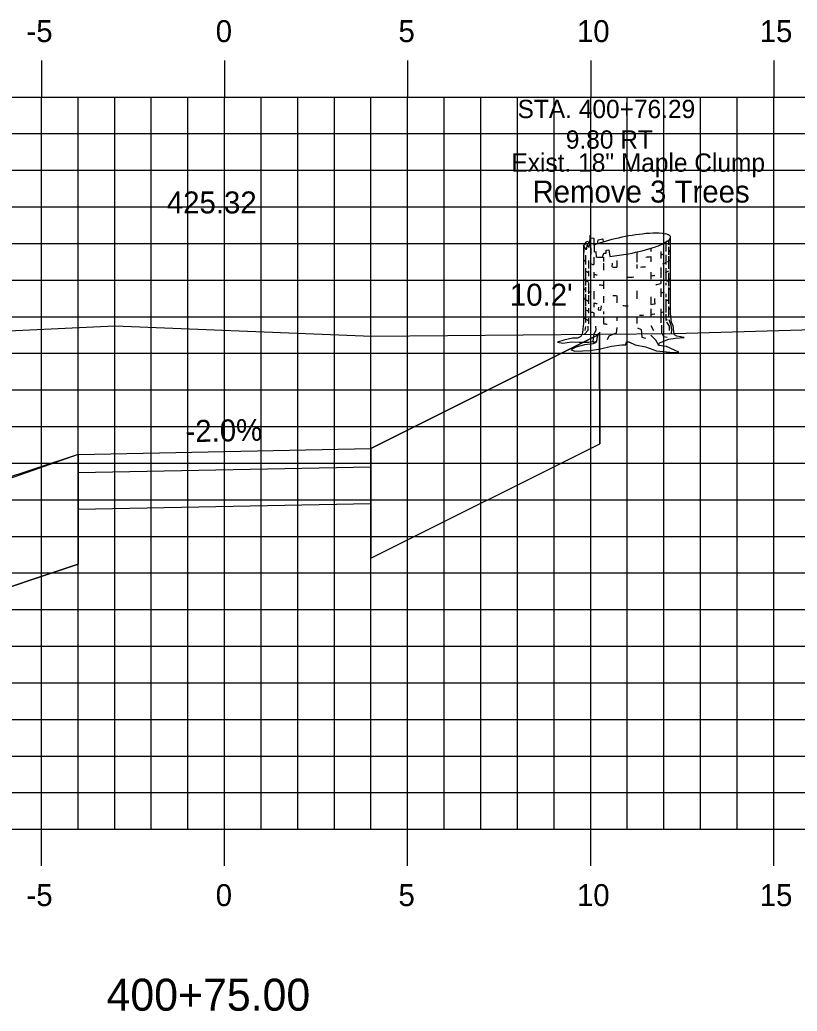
# Model space of a CAD drawing. Extents: x -161 to 764, y 111 to 210.
# Drawn here: x 405 to 426.23, y 171.28 to 198.36 of the extents above; entities that cross this region are included whole.
import ezdxf

# ---------------------------------------------------------------- set-up
doc = ezdxf.new("R2010")
doc.units = 0
for name, color, linetype in [('D_Property_Walkway_Paved', 7, 'Continuous'), ('D_Roadway_Centerline_Text', 7, 'Continuous'), ('D_Roadway_SubGrade', 7, 'Continuous'), ('D_Slope_Cut', 7, 'Continuous'), ('D_Text_Monospaced', 7, 'Continuous'), ('D_Text_Standard', 7, 'Continuous'), ('H_V ANNOTATION', 7, 'Continuous'), ('MAJOR', 7, 'Continuous'), ('MINOR', 7, 'Continuous'), ('PATTERNING', 7, 'Continuous'), ('S_Roadway_Centerline', 7, 'Continuous'), ('S_Trees_Decid_Pay', 7, 'Continuous')]:
    doc.layers.add(name, color=color, linetype=linetype)

msp = doc.modelspace()

# ---------------------------------------------------------------- linework, layer by layer
at = {"layer": 'D_Property_Walkway_Paved'}
for p, q in [((414.591, 186.147), (414.591, 186.647)), ((406.591, 186.487), (406.591, 185.987))]:
    msp.add_line(p, q, dxfattribs=at)
for points in [[(406.591, 186.487), (414.591, 186.647)], [(406.591, 185.987), (414.591, 186.147)]]:
    msp.add_lwpolyline(points, dxfattribs=at)
at = {"layer": 'D_Roadway_SubGrade'}
msp.add_line((414.591, 185.147), (414.591, 186.147), dxfattribs=at)
msp.add_lwpolyline([(406.591, 185.987), (406.591, 184.987), (414.591, 185.147)], dxfattribs=at)
at = {"layer": 'D_Slope_Cut'}
for p, q in [((414.591, 186.647), (420.832, 189.768)), ((420.832, 189.768), (420.845, 186.774)), ((406.591, 186.487), (403.591, 185.487)), ((406.591, 186.487), (406.591, 183.487))]:
    msp.add_line(p, q, dxfattribs=at)
for points in [[(414.591, 186.647), (414.591, 183.647), (420.845, 186.774)], [(406.591, 183.487), (403.591, 182.487), (395.592, 186.488)]]:
    msp.add_lwpolyline(points, dxfattribs=at)
at = {"layer": 'MAJOR'}
for p, q in [((405.591, 197.249), (405.591, 196.247)), ((410.591, 197.249), (410.591, 196.247)), ((415.591, 197.249), (415.591, 196.247)), ((420.591, 197.249), (420.591, 196.247)), ((425.591, 197.249), (425.591, 196.247)), ((340.591, 196.247), (480.591, 196.247)), ((340.591, 196.247), (480.591, 196.247)), ((405.591, 176.247), (405.591, 196.247)), ((410.591, 176.247), (410.591, 196.247)), ((415.591, 176.247), (415.591, 196.247)), ((420.591, 176.247), (420.591, 196.247)), ((425.591, 176.247), (425.591, 196.247)), ((340.591, 191.247), (480.591, 191.247)), ((340.591, 186.247), (480.591, 186.247)), ((340.591, 181.247), (480.591, 181.247)), ((340.591, 176.247), (480.591, 176.247)), ((340.591, 176.247), (480.591, 176.247)), ((405.591, 175.245), (405.591, 176.247)), ((410.591, 175.245), (410.591, 176.247)), ((415.591, 175.245), (415.591, 176.247)), ((420.591, 175.245), (420.591, 176.247)), ((425.591, 175.245), (425.591, 176.247))]:
    msp.add_line(p, q, dxfattribs=at)
at = {"layer": 'MINOR'}
for p, q in [((406.591, 176.247), (406.591, 196.247)), ((407.591, 176.247), (407.591, 196.247)), ((408.591, 176.247), (408.591, 196.247)), ((409.591, 176.247), (409.591, 196.247)), ((411.591, 176.247), (411.591, 196.247)), ((412.591, 176.247), (412.591, 196.247)), ((413.591, 176.247), (413.591, 196.247)), ((414.591, 176.247), (414.591, 196.247)), ((416.591, 176.247), (416.591, 196.247)), ((417.591, 176.247), (417.591, 196.247)), ((418.591, 176.247), (418.591, 196.247)), ((419.591, 176.247), (419.591, 196.247)), ((421.591, 176.247), (421.591, 196.247)), ((422.591, 176.247), (422.591, 196.247)), ((423.591, 176.247), (423.591, 196.247)), ((424.591, 176.247), (424.591, 196.247)), ((340.591, 195.247), (480.591, 195.247)), ((340.591, 194.247), (480.591, 194.247)), ((340.591, 193.247), (480.591, 193.247)), ((340.591, 192.247), (480.591, 192.247)), ((340.591, 190.247), (480.591, 190.247)), ((340.591, 189.247), (480.591, 189.247)), ((340.591, 188.247), (480.591, 188.247)), ((340.591, 187.247), (480.591, 187.247)), ((340.591, 185.247), (480.591, 185.247)), ((340.591, 184.247), (480.591, 184.247)), ((340.591, 183.247), (480.591, 183.247)), ((340.591, 182.247), (480.591, 182.247)), ((340.591, 180.247), (480.591, 180.247)), ((340.591, 179.247), (480.591, 179.247)), ((340.591, 178.247), (480.591, 178.247)), ((340.591, 177.247), (480.591, 177.247))]:
    msp.add_line(p, q, dxfattribs=at)
at = {"layer": 'PATTERNING'}
for points in [[(414.591, 186.647), (414.591, 183.647), (420.845, 186.774), (420.832, 189.768)], [(395.597, 189.484), (395.592, 186.488), (403.591, 182.487), (406.591, 183.487), (406.591, 186.487), (403.592, 185.431)]]:
    msp.add_lwpolyline(points, close=True, dxfattribs=at)
at = {"layer": 'S_Roadway_Centerline'}
msp.add_lwpolyline([(340.591, 183.558), (346.27, 184.146), (348.315, 184.806), (354.074, 186.337), (357.168, 187.075), (364.507, 188.564), (366.124, 189.037), (373.039, 189.084), (380.424, 189.717), (384.106, 189.757), (390.092, 189.37), (397.718, 189.529), (407.599, 189.997), (414.618, 189.716), (422.879, 189.785), (430.793, 190.018)], dxfattribs=at)
at = {"layer": 'S_Trees_Decid_Pay'}
for p, q in [((422.64, 192.283), (422.64, 192.03)), ((422.72, 192.327), (422.72, 192.207)), ((420.595, 192.124), (420.595, 191.95)), ((421.852, 192.015), (421.852, 191.735)), ((422.235, 192.116), (422.235, 192.03)), ((422.507, 192.03), (422.507, 191.838)), ((422.72, 192.155), (422.72, 191.941)), ((420.446, 191.924), (420.446, 191.669)), ((420.532, 191.778), (420.532, 191.566)), ((420.68, 191.875), (420.68, 191.671)), ((420.941, 191.877), (420.941, 191.758)), ((421.306, 191.778), (421.306, 191.598)), ((422.235, 191.888), (422.235, 191.749)), ((422.64, 191.933), (422.64, 191.669)), ((422.72, 191.896), (422.72, 191.558)), ((420.446, 191.572), (420.446, 191.103)), ((420.532, 191.501), (420.532, 191.352)), ((420.68, 191.463), (420.68, 191.309)), ((420.941, 191.706), (420.941, 191.521)), ((421.179, 191.606), (421.185, 191.713)), ((421.852, 191.669), (421.852, 191.566)), ((422.235, 191.463), (422.235, 191.272)), ((422.507, 191.587), (422.507, 191.309)), ((422.64, 191.572), (422.64, 191.264)), ((420.532, 191.175), (420.532, 190.875)), ((420.941, 191.235), (420.941, 191.007)), ((422.507, 191.264), (422.507, 191.155)), ((422.64, 191.175), (422.64, 191.109)), ((422.72, 191.441), (422.72, 191.08)), ((420.446, 191.052), (420.446, 190.918)), ((420.68, 190.946), (420.68, 190.726)), ((421.852, 190.955), (421.852, 190.734)), ((422.507, 191.02), (422.507, 190.792)), ((422.72, 191.043), (422.72, 190.595)), ((420.446, 190.86), (420.446, 190.535)), ((420.532, 190.837), (420.532, 190.595)), ((420.941, 190.808), (420.941, 190.623)), ((421.306, 190.82), (421.306, 190.623)), ((422.235, 190.792), (422.235, 190.584)), ((422.64, 190.875), (422.64, 190.778)), ((422.64, 190.726), (422.64, 190.366)), ((420.446, 190.506), (420.446, 190.086)), ((420.532, 190.484), (420.532, 190.343)), ((420.68, 190.627), (420.68, 190.506)), ((420.941, 190.388), (420.941, 190.312)), ((422.235, 190.463), (422.235, 190.263)), ((422.507, 190.463), (422.507, 190.079)), ((422.72, 190.529), (422.72, 190.247)), ((420.532, 190.211), (420.532, 190.055)), ((420.68, 190.355), (420.68, 190.257)), ((420.941, 190.234), (420.941, 190.061)), ((421.306, 190.24), (421.306, 190.137)), ((421.852, 190.234), (421.852, 190.061)), ((422.64, 190.314), (422.64, 190.148)), ((420.449, 189.983), (420.435, 189.866)), ((422.23, 190.006), (422.311, 189.874))]:
    msp.add_line(p, q, dxfattribs=at)
for points in [[(420.395, 192.198), (420.395, 190.061), (420.375, 189.919), (420.369, 189.793), (420.326, 189.707), (420.233, 189.658), (420.097, 189.658), (419.854, 189.602), (419.687, 189.553), (419.83, 189.522), (420.066, 189.559), (420.276, 189.547), (420.538, 189.553), (420.662, 189.571), (420.692, 189.528), (420.754, 189.571), (420.655, 189.503), (420.42, 189.478), (420.19, 189.417), (420.06, 189.346), (420.159, 189.303), (420.581, 189.322), (420.859, 189.366), (421.158, 189.442), (421.444, 189.478), (421.549, 189.478), (421.567, 189.559), (421.635, 189.565), (421.802, 189.478), (422.088, 189.423), (422.387, 189.316), (422.846, 189.266), (423, 189.279), (422.658, 189.429), (422.455, 189.46), (422.467, 189.534), (422.727, 189.633), (422.902, 189.664), (423.143, 189.676), (422.944, 189.713), (422.883, 189.75), (422.858, 189.837), (422.846, 190.006), (422.801, 190.092), (422.772, 190.333), (422.772, 192.419)], [(420.751, 191.871), (420.744, 192.015), (420.698, 192.007), (420.684, 192.382), (420.589, 192.39), (420.575, 192.47), (420.538, 192.133), (420.492, 192.227), (420.472, 192.073), (420.395, 192.198), (420.401, 192.009)], [(420.395, 192.198), (420.441, 192.221), (420.463, 192.287), (420.515, 192.31), (420.549, 192.235)], [(420.774, 192.237), (420.795, 192.345), (420.927, 192.375), (420.934, 192.287)], [(420.913, 191.875), (420.95, 191.978), (421.015, 191.984), (421.015, 192.066), (421.089, 192.073), (421.114, 191.892)], [(422.349, 190.598), (422.347, 190.675), (422.339, 190.741)], [(420.803, 190.506), (420.795, 190.432), (420.869, 190.426), (420.883, 190.543)], [(422.665, 190.094), (422.736, 189.991), (422.736, 189.866)], [(422.722, 190.175), (422.782, 190.014), (422.796, 189.888), (422.788, 189.791)], [(420.515, 189.991), (420.509, 189.866), (420.427, 189.771)], [(420.662, 189.571), (420.68, 189.75), (420.742, 189.887), (420.735, 189.987)], [(421.304, 189.954), (421.287, 189.8), (421.089, 189.719), (421.044, 189.616)], [(421.87, 189.946), (421.973, 189.894), (421.987, 189.688), (422.09, 189.659)], [(422.524, 190.02), (422.524, 189.814), (422.582, 189.705), (422.679, 189.688)], [(420.853, 189.818), (420.778, 189.75), (420.76, 189.652), (420.754, 189.571)], [(422.455, 189.46), (422.368, 189.602), (422.236, 189.744)]]:
    msp.add_lwpolyline(points, dxfattribs=at)
for centre, radius, start, end in [((422.685, 186.417), 6.126, 93.6944, 100.7779), ((422.374, 191.233), 1.299, 78.2779, 93.6944), ((422.685, 186.417), 6.126, 100.7779, 107.8613), ((421.963, 193.392), 1.299, 287.8613, 303.2779), ((422.541, 192.036), 0.48, 69.9843, 78.2779), ((422.413, 192.707), 0.48, 303.2779, 311.5714), ((422.649, 192.333), 0.164, 55.7779, 69.9843), ((422.622, 192.471), 0.164, 311.5714, 325.7779), ((422.681, 192.38), 0.107, 45.9547, 55.7779), ((422.71, 192.41), 0.0645, 33.2779, 45.9547), ((422.669, 192.439), 0.107, 325.7779, 335.6011), ((422.719, 192.416), 0.0544, 22.46, 33.2779), ((422.708, 192.421), 0.0645, 335.6011, 348.2779), ((422.726, 192.419), 0.0467, 10.7779, 22.46), ((422.718, 192.419), 0.0544, 348.2779, 359.0957), ((422.726, 192.419), 0.0467, 359.0957, 10.7779), ((421.205, 191.011), 1.299, 107.8613, 113.3069), ((420.483, 197.986), 6.126, 280.7779, 287.8613), ((422.633, 192.162), 0.166, 301.67, 315), ((422.673, 192.121), 0.109, 315, 324.8263), ((422.709, 192.096), 0.0657, 324.8263, 337.5), ((422.718, 192.092), 0.0554, 337.5, 348.3185), ((420.443, 191.83), 0.0476, 180, 191.6815), ((420.451, 191.831), 0.0554, 191.6815, 202.5), ((420.46, 191.835), 0.0657, 202.5, 215.1737), ((420.496, 191.86), 0.109, 215.1737, 225), ((420.536, 191.901), 0.166, 225, 239.1924), ((420.794, 193.169), 1.299, 268.1289, 273.6944), ((420.483, 197.986), 6.126, 273.6944, 274.0246), ((420.483, 197.986), 6.126, 275.9147, 280.7779), ((421.585, 197.769), 5.916, 274.9514, 276.3087), ((422.161, 193.181), 1.292, 285.5651, 289.0916), ((422.16, 192.92), 1.292, 288.0829, 292.5), ((422.469, 192.174), 0.484, 297.4162, 300.8076), ((422.632, 191.901), 0.166, 300.8076, 315), ((422.672, 191.86), 0.109, 315, 324.8263), ((422.708, 191.835), 0.0657, 324.8263, 337.5), ((422.717, 191.831), 0.0554, 337.5, 348.3185), ((420.536, 191.637), 0.166, 237.0378, 239.1924), ((420.699, 191.91), 0.484, 239.1924, 247.5), ((421.008, 192.657), 1.292, 247.5, 248.3537), ((421.008, 192.92), 1.292, 250.6119, 255.2856), ((421.584, 197.508), 5.916, 266.0776, 267.3043), ((421.584, 197.508), 5.916, 273.5382, 274.8924), ((422.16, 192.657), 1.292, 291.8071, 292.5), ((422.469, 191.91), 0.484, 292.5, 300.8076), ((422.632, 191.637), 0.166, 300.8076, 301.6001), ((420.443, 191.309), 0.0476, 180, 191.6815), ((420.451, 191.311), 0.0554, 191.6815, 202.5), ((420.46, 191.314), 0.0657, 202.5, 215.1737), ((420.496, 191.339), 0.109, 215.1737, 225), ((420.536, 191.38), 0.166, 225, 239.1924), ((420.699, 191.653), 0.484, 239.1924, 245.7724), ((421.008, 192.399), 1.292, 247.5, 248.4842), ((421.008, 192.657), 1.292, 255.2856, 259.2632), ((421.584, 197.245), 5.916, 270.1162, 271.7708), ((421.584, 197.245), 5.916, 276.3183, 277.1546), ((422.16, 192.657), 1.292, 277.1546, 278.3662), ((422.469, 191.653), 0.484, 294.6372, 300.8076), ((422.632, 191.38), 0.166, 300.8076, 315), ((422.672, 191.339), 0.109, 315, 324.8263), ((422.708, 191.314), 0.0657, 324.8263, 337.5), ((422.717, 191.311), 0.0554, 337.5, 348.3185), ((420.443, 191.052), 0.0476, 180, 191.6815), ((420.451, 191.053), 0.0554, 191.6815, 202.5), ((420.46, 191.057), 0.0657, 202.5, 215.1737), ((420.496, 191.082), 0.109, 215.1737, 225), ((420.536, 191.123), 0.166, 225, 239.1924), ((421.008, 192.142), 1.292, 247.5, 251.799), ((421.008, 192.399), 1.292, 261.8726, 262.8454), ((421.584, 196.987), 5.916, 262.8454, 263.7595), ((422.16, 192.399), 1.292, 279.2565, 285.6105), ((422.16, 192.142), 1.292, 285.6105, 290.1001), ((422.632, 191.123), 0.166, 302.0694, 315), ((422.672, 191.082), 0.109, 315, 324.8263), ((422.708, 191.057), 0.0657, 324.8263, 337.5), ((422.717, 191.053), 0.0554, 337.5, 348.3185), ((420.443, 190.786), 0.0476, 180, 191.6815), ((420.451, 190.788), 0.0554, 191.6815, 202.5), ((420.46, 190.791), 0.0657, 202.5, 215.1737), ((420.496, 190.816), 0.109, 215.1737, 225), ((420.536, 190.857), 0.166, 225, 239.1924), ((420.699, 191.13), 0.484, 239.1924, 247.5), ((421.008, 191.876), 1.292, 247.5, 248.3537), ((421.584, 196.73), 5.916, 266.2721, 267.3043), ((422.469, 191.13), 0.484, 292.5, 300.8076), ((422.632, 190.857), 0.166, 300.8076, 302.0694), ((422.717, 190.788), 0.0554, 337.5, 348.3185), ((420.699, 190.858), 0.484, 242.734, 247.5), ((421.008, 191.604), 1.292, 251.3664, 255.2856), ((421.008, 191.876), 1.292, 255.2856, 259.2463), ((421.584, 196.464), 5.916, 268.9206, 270), ((421.584, 196.464), 5.916, 270, 270.2757), ((421.584, 196.464), 5.916, 276.3183, 277.1546), ((422.16, 191.876), 1.292, 277.1546, 278.3795), ((422.16, 191.604), 1.292, 285.6105, 289.1534), ((422.632, 190.585), 0.166, 302.0694, 315), ((422.672, 190.545), 0.109, 315, 324.8263), ((422.708, 190.52), 0.0657, 324.8263, 337.5), ((422.717, 190.516), 0.0554, 337.5, 348.3185), ((420.443, 190.257), 0.0476, 180, 191.6815), ((420.451, 190.258), 0.0554, 191.6815, 202.5), ((420.46, 190.262), 0.0657, 202.5, 215.1737), ((420.496, 190.287), 0.109, 215.1737, 225), ((420.536, 190.328), 0.166, 225, 239.1924), ((420.699, 190.601), 0.484, 239.1924, 247.5), ((421.008, 191.347), 1.292, 247.5, 248.3537), ((421.584, 196.192), 5.916, 273.2637, 274.461), ((421.584, 196.192), 5.916, 276.3183, 277.1546), ((422.16, 191.604), 1.292, 277.1546, 278.3662), ((422.169, 191.351), 1.292, 291.3696, 292.0604), ((422.469, 190.601), 0.484, 292.5, 296.5499), ((421.584, 195.935), 5.916, 263.7831, 264.7655)]:
    msp.add_arc(centre, radius, start, end, dxfattribs=at)

# ---------------------------------------------------------------- texts
at = {"layer": 'D_Roadway_Centerline_Text'}
msp.add_text('425.32', height=0.6, dxfattribs=at).set_placement((409.015, 193.068))
at = {"layer": 'D_Text_Monospaced'}
for s, height, p in [('STA. 400+76.29', 0.49998, (418.595, 195.671)), ('9.80 RT', 0.5, (419.912, 194.837)), ('Exist. 18" Maple Clump', 0.49998, (418.428, 194.207))]:
    msp.add_text(s, height=height, dxfattribs=at).set_placement(p)
at = {"layer": 'D_Text_Standard'}
for s, p in [('Remove 3 Trees', (419.002, 193.365)), ("10.2'", (418.384, 190.547))]:
    msp.add_text(s, height=0.6, dxfattribs=at).set_placement(p)
msp.add_text('-2.0%', height=0.6, rotation=1.1458, dxfattribs=at).set_placement((409.53, 186.818))
at = {"layer": 'H_V ANNOTATION'}
for s, height, p in [('-5', 0.6, (405.182, 197.747)), ('0', 0.6, (410.35, 197.747)), ('5', 0.6, (415.342, 197.747)), ('10', 0.6, (420.216, 197.747)), ('15', 0.6, (425.208, 197.747)), ('-5', 0.6, (405.182, 174.147)), ('0', 0.6, (410.35, 174.147)), ('5', 0.6, (415.342, 174.147)), ('10', 0.6, (420.216, 174.147)), ('15', 0.6, (425.208, 174.147)), ('400+75.00', 0.875, (407.368, 171.29))]:
    msp.add_text(s, height=height, rotation=360, dxfattribs=at).set_placement(p)

doc.saveas('drawing.dxf')
